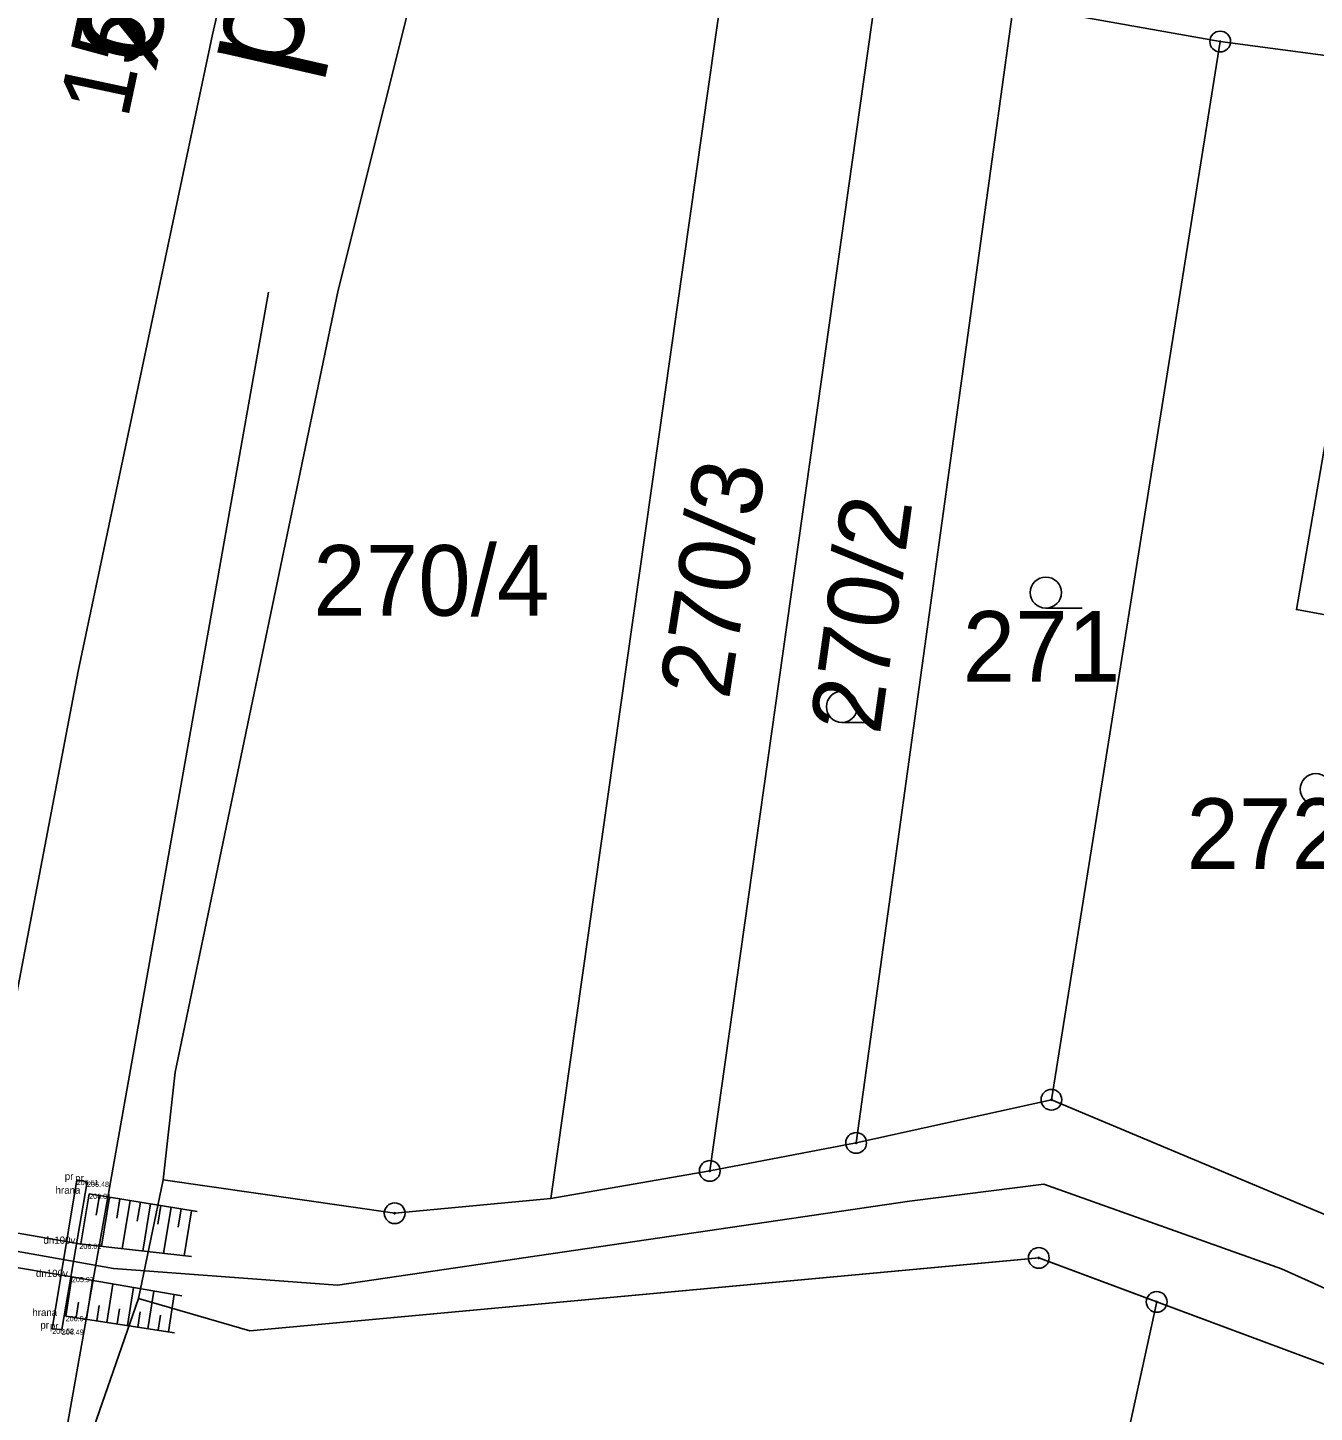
# Model space of a CAD drawing. Extents: x -537341 to -532984, y -1143469 to -1141314.
# Drawn here: x -534544.9 to -534482.9, y -1142960.5 to -1142893.8 of the extents above; entities that cross this region are included whole.
import ezdxf

# ---------------------------------------------------------------- set-up
doc = ezdxf.new("R2010")
doc.units = 0
for name, color, linetype in [('Hranice parcel', 7, 'Continuous'), ('parcelní_č_2000', 7, 'Continuous'), ('u_obec_Horní_Moš', 7, 'Continuous'), ('u_objekty', 7, 'Continuous'), ('u_osa_toku', 7, 'Continuous'), ('u_pricne', 7, 'Continuous'), ('U_SOUKROMÉ', 7, 'Continuous'), ('u_ŘSD', 7, 'Continuous'), ('Vnitřní kresba', 7, 'Continuous'), ('Značky bodu BP', 7, 'Continuous'), ('Značky kultur', 7, 'Continuous'), ('ˇ1', 7, 'Continuous'), ('ˇ12', 7, 'Continuous'), ('ˇ13', 7, 'Continuous'), ('ˇ18', 7, 'Continuous'), ('ˇ3', 7, 'Continuous'), ('ˇ8', 7, 'Continuous'), ('ˇ9', 7, 'Continuous')]:
    doc.layers.add(name, color=color, linetype=linetype)

msp = doc.modelspace()

# ---------------------------------------------------------------- linework, layer by layer
at = {"layer": 'Hranice parcel'}
for p, q in [((-534511.19, -1142890.39), (-534519.65, -1142950.19)), ((-534503.94, -1142891.72), (-534512, -1142948.86)), ((-534504.95, -1142947.51), (-534497.37, -1142892.68)), ((-534487.41, -1142894.45), (-534497.37, -1142892.68)), ((-534495.54, -1142945.43), (-534487.41, -1142894.45)), ((-534487.41, -1142894.45), (-534479.21, -1142895.54)), ((-534504.95, -1142947.51), (-534495.54, -1142945.43)), ((-534512, -1142948.86), (-534504.95, -1142947.51)), ((-534519.65, -1142950.19), (-534512, -1142948.86)), ((-534538.34, -1142949.29), (-534539.53, -1142955)), ((-534490.47, -1142955.17), (-534497.26, -1142986.3))]:
    msp.add_line(p, q, dxfattribs=at)
for points in [[(-534525.43, -1142888.52), (-534529.91, -1142906.42), (-534537.75, -1142944.1), (-534538.34, -1142949.29)], [(-534479.21, -1142895.54), (-534482.74, -1142916.04), (-534483.74, -1142921.82), (-534476.77, -1142923.1), (-534476.75, -1142923), (-534474.1, -1142923.43), (-534470.9, -1142923.96)], [(-534475.26, -1142953.95), (-534485.86, -1142949.5), (-534495.54, -1142945.43)], [(-534538.34, -1142949.29), (-534527.18, -1142950.9), (-534519.65, -1142950.19)], [(-534490.47, -1142955.17), (-534496.15, -1142953.05), (-534534.16, -1142956.56), (-534539.53, -1142955)], [(-534539.53, -1142955), (-534542.49, -1142963.57), (-534543.19, -1142971.37)], [(-534397.75, -1143018.75), (-534397.18, -1143016.27), (-534448.4, -1142984.98), (-534459.62, -1142976.04), (-534479.17, -1142959.38), (-534490.47, -1142955.17)]]:
    msp.add_lwpolyline(points, dxfattribs=at)
at = {"layer": 'u_obec_Horní_Moš'}
for p, q in [((-534495.54, -1142945.43), (-534504.95, -1142947.51)), ((-534504.95, -1142947.51), (-534512, -1142948.86)), ((-534512, -1142948.86), (-534519.65, -1142950.19)), ((-534538.34, -1142949.29), (-534539.53, -1142955)), ((-534534.16, -1142956.56), (-534496.648, -1142953.096)), ((-534539.53, -1142955), (-534534.16, -1142956.56))]:
    msp.add_line(p, q, dxfattribs=at)
for points in [[(-534475.26, -1142953.95), (-534485.86, -1142949.5), (-534495.54, -1142945.43)], [(-534519.65, -1142950.19), (-534527.18, -1142950.9), (-534538.34, -1142949.29)], [(-534496.648, -1142953.096), (-534496.15, -1142953.05), (-534495.682, -1142953.225), (-534490.938, -1142954.995), (-534490.47, -1142955.17)], [(-534490.47, -1142955.17), (-534490.001, -1142955.345), (-534479.639, -1142959.205)]]:
    msp.add_lwpolyline(points, dxfattribs=at)
at = {"layer": 'u_osa_toku'}
msp.add_lwpolyline([(-534623.017, -1142940.808), (-534607.282, -1142942.643), (-534587.693, -1142944.646), (-534576.649, -1142947.17), (-534561.658, -1142949.835), (-534540.722, -1142953.556), (-534529.931, -1142954.371), (-534502.381, -1142950.31), (-534495.908, -1142949.498), (-534484.457, -1142953.581), (-534476.389, -1142957.2)], dxfattribs=at)
at = {"layer": 'u_pricne'}
msp.add_line((-534533.254, -1142906.523), (-534552.634, -1143015.552), dxfattribs=at)
at = {"layer": 'U_SOUKROMÉ'}
for p, q in [((-534496.648, -1142953.096), (-534534.16, -1142956.56)), ((-534490.938, -1142954.995), (-534495.682, -1142953.225)), ((-534539.53, -1142955), (-534542.49, -1142963.57)), ((-534534.16, -1142956.56), (-534539.53, -1142955)), ((-534497.26, -1142986.3), (-534490.47, -1142955.17)), ((-534490.47, -1142955.17), (-534497.26, -1142986.3)), ((-534490.47, -1142955.17), (-534490.938, -1142954.995))]:
    msp.add_line(p, q, dxfattribs=at)
for points in [[(-534495.682, -1142953.225), (-534496.15, -1142953.05), (-534496.648, -1142953.096)], [(-534479.639, -1142959.205), (-534490.001, -1142955.345), (-534490.47, -1142955.17)]]:
    msp.add_lwpolyline(points, dxfattribs=at)
at = {"layer": 'u_ŘSD'}
for p, q in [((-534535.95, -1142894.11), (-534530.06, -1142867.8)), ((-534530.06, -1142867.8), (-534535.95, -1142894.11)), ((-534542.43, -1142924.78), (-534535.95, -1142894.11)), ((-534535.95, -1142894.11), (-534542.43, -1142924.78)), ((-534547.45, -1142951.09), (-534542.43, -1142924.78)), ((-534542.43, -1142924.78), (-534547.45, -1142951.09)), ((-534539.53, -1142955), (-534538.34, -1142949.29)), ((-534542.49, -1142963.57), (-534539.53, -1142955))]:
    msp.add_line(p, q, dxfattribs=at)
msp.add_lwpolyline([(-534538.34, -1142949.29), (-534537.75, -1142944.1), (-534529.91, -1142906.42), (-534525.43, -1142888.52)], dxfattribs=at)
at = {"layer": 'Vnitřní kresba'}
for p, q in [((-534535.95, -1142894.11), (-534530.06, -1142867.8)), ((-534542.43, -1142924.78), (-534535.95, -1142894.11)), ((-534547.45, -1142951.09), (-534542.43, -1142924.78))]:
    msp.add_line(p, q, dxfattribs=at)
at = {"layer": 'Značky bodu BP'}
for centre, radius in [((-534487.41, -1142894.45), 0.5), ((-534487.41, -1142894.45), 0.0303), ((-534495.54, -1142945.43), 0.5), ((-534495.54, -1142945.43), 0.0303), ((-534504.95, -1142947.51), 0.5), ((-534504.95, -1142947.51), 0.0303), ((-534512, -1142948.86), 0.5), ((-534512, -1142948.86), 0.0303), ((-534527.18, -1142950.9), 0.5), ((-534527.18, -1142950.9), 0.0303), ((-534496.15, -1142953.05), 0.5), ((-534496.15, -1142953.05), 0.0303), ((-534490.47, -1142955.17), 0.5), ((-534490.47, -1142955.17), 0.0303)]:
    msp.add_circle(centre, radius, dxfattribs=at)
at = {"layer": 'Značky kultur'}
for p, q in [((-534495.813, -1142921.75), (-534494.063, -1142921.75)), ((-534505.633, -1142927.25), (-534503.883, -1142927.25))]:
    msp.add_line(p, q, dxfattribs=at)
for centre in [(-534495.813, -1142921), (-534505.633, -1142926.5), (-534482.803, -1142930.47)]:
    msp.add_circle(centre, 0.75, dxfattribs=at)
at = {"layer": 'ˇ1'}
for p, q in [((-534542.5, -1142949.29), (-534542.5, -1142949.29)), ((-534542.5, -1142949.29), (-534542.5, -1142949.29)), ((-534542, -1142949.38), (-534542, -1142949.38)), ((-534542, -1142949.38), (-534542, -1142949.38)), ((-534541.9, -1142949.96), (-534541.9, -1142949.96)), ((-534541.9, -1142949.96), (-534541.9, -1142949.96)), ((-534542.37, -1142952.37), (-534542.37, -1142952.37)), ((-534542.37, -1142952.37), (-534542.37, -1142952.37)), ((-534542.73, -1142953.97), (-534542.73, -1142953.97)), ((-534542.73, -1142953.97), (-534542.73, -1142953.97)), ((-534543.03, -1142955.85), (-534543.03, -1142955.85)), ((-534543.03, -1142955.85), (-534543.03, -1142955.85)), ((-534543.68, -1142956.46), (-534543.68, -1142956.46)), ((-534543.68, -1142956.46), (-534543.68, -1142956.46)), ((-534543.22, -1142956.5), (-534543.22, -1142956.5)), ((-534543.22, -1142956.5), (-534543.22, -1142956.5))]:
    msp.add_line(p, q, dxfattribs=at)
at = {"layer": 'ˇ12'}
for p, q in [((-534541.9, -1142949.96), (-534536.7, -1142950.82)), ((-534542.37, -1142952.37), (-534536.97, -1142952.99)), ((-534542.73, -1142953.97), (-534537.43, -1142954.88)), ((-534543.02, -1142955.85), (-534537.79, -1142956.66))]:
    msp.add_line(p, q, dxfattribs=at)
at = {"layer": 'ˇ13'}
for p, q in [((-534541.9, -1142949.96), (-534542.3, -1142952.378)), ((-534541.407, -1142950.042), (-534541.565, -1142950.999)), ((-534540.913, -1142950.123), (-534541.305, -1142952.492)), ((-534540.42, -1142950.205), (-534540.575, -1142951.143)), ((-534539.927, -1142950.286), (-534540.311, -1142952.606)), ((-534539.434, -1142950.368), (-534539.585, -1142951.286)), ((-534538.94, -1142950.45), (-534539.316, -1142952.721)), ((-534538.447, -1142950.531), (-534538.596, -1142951.43)), ((-534537.954, -1142950.613), (-534538.321, -1142952.835)), ((-534537.46, -1142950.694), (-534537.606, -1142951.573)), ((-534536.967, -1142950.776), (-534537.326, -1142952.949)), ((-534543.02, -1142955.85), (-534542.729, -1142953.97)), ((-534542.032, -1142956.003), (-534541.743, -1142954.139)), ((-534541.044, -1142956.156), (-534540.758, -1142954.309)), ((-534540.055, -1142956.309), (-534539.771, -1142954.478)), ((-534539.067, -1142956.462), (-534538.786, -1142954.647)), ((-534538.079, -1142956.615), (-534537.8, -1142954.816)), ((-534542.526, -1142955.927), (-534542.41, -1142955.178)), ((-534541.538, -1142956.08), (-534541.423, -1142955.337)), ((-534540.549, -1142956.233), (-534540.435, -1142955.497)), ((-534539.561, -1142956.386), (-534539.448, -1142955.656)), ((-534538.573, -1142956.539), (-534538.461, -1142955.816))]:
    msp.add_line(p, q, dxfattribs=at)
at = {"layer": 'ˇ8'}
for p, q in [((-534562.36, -1142948.92), (-534542.37, -1142952.37)), ((-534542.73, -1142953.97), (-534562.65, -1142950.55))]:
    msp.add_line(p, q, dxfattribs=at)
at = {"layer": 'ˇ9'}
for p, q in [((-534543.68, -1142956.46), (-534542.5, -1142949.29)), ((-534542, -1142949.38), (-534543.22, -1142956.5)), ((-534542.5, -1142949.29), (-534542, -1142949.38)), ((-534543.22, -1142956.5), (-534543.68, -1142956.46))]:
    msp.add_line(p, q, dxfattribs=at)

# ---------------------------------------------------------------- texts
at = {"layer": 'parcelní_č_2000'}
for s, rotation, p in [('1541/1', 78, (-534540.045, -1142898.237)), ('270/3', 81, (-534511.084, -1142926.208)), ('270/2', 82, (-534503.81, -1142927.896))]:
    msp.add_text(s, height=3.4, rotation=rotation, dxfattribs=at).set_placement(p)
for s, p in [('270/4', (-534531.106, -1142922.11)), ('271', (-534499.814, -1142925.29)), ('272/1', (-534489.035, -1142934.31))]:
    msp.add_text(s, height=3.4, dxfattribs=at).set_placement(p)
at = {"layer": 'u_objekty'}
for s, p in [('propustek 2xDN1000', (-534532.084, -1142896.254)), ('ø. km 10,524-10,544', (-534538.846, -1142895.978))]:
    msp.add_text(s, height=5, rotation=77.11969, dxfattribs=at).set_placement(p)
at = {"layer": 'ˇ18'}
for s, p in [('pr', (-534543.073, -1142949.29)), ('pr', (-534542.573, -1142949.38)), ('hrana', (-534543.52, -1142949.96)), ('dn100v', (-534544.103, -1142952.37)), ('dn100v', (-534544.463, -1142953.97)), ('hrana', (-534544.64, -1142955.85)), ('pr', (-534544.253, -1142956.46)), ('pr', (-534543.793, -1142956.5))]:
    msp.add_text(s, height=0.35, dxfattribs=at).set_placement(p)
at = {"layer": 'ˇ3'}
for s, p in [('206.51 ', (-534542.5, -1142949.54)), ('206.48 ', (-534542, -1142949.63)), ('206.01 ', (-534541.9, -1142950.21)), ('206.02 ', (-534542.37, -1142952.62)), ('205.97 ', (-534542.73, -1142954.22)), ('206.04 ', (-534543.03, -1142956.1)), ('206.52 ', (-534543.68, -1142956.71)), ('206.49 ', (-534543.22, -1142956.75))]:
    msp.add_text(s, height=0.25, dxfattribs=at).set_placement(p)

doc.saveas('drawing.dxf')
